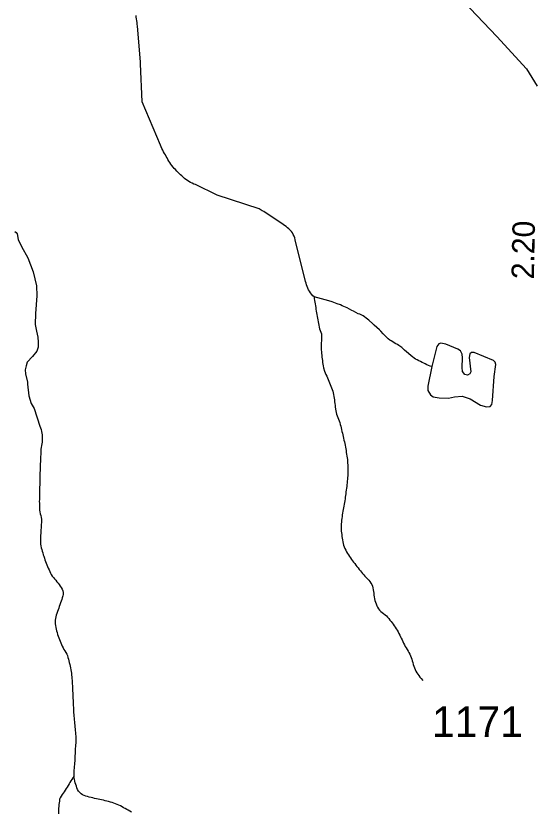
# Model space of a CAD drawing. Extents: x 1950930 to 2061844, y 904556 to 1017002.
# Drawn here: x 1966393 to 1969289, y 930923 to 935352 of the extents above; entities that cross this region are included whole.
import ezdxf

# ---------------------------------------------------------------- set-up
doc = ezdxf.new("R2010")
doc.units = 0
for name, color, linetype in [('Exist Hydrographic Creek Single Shore', 7, 'Continuous'), ('Exist Hydrographic Misc Water Feature', 7, 'Continuous'), ('Exist Road Primary US Structure Standard Bridge CELL', 7, 'Continuous'), ('Exist Road Secondary Type 51 Attributed', 7, 'Continuous'), ('Exist Road Secondary Type 51 Number Label', 7, 'Continuous')]:
    doc.layers.add(name, color=color, linetype=linetype)

msp = doc.modelspace()

# ---------------------------------------------------------------- linework, layer by layer
at = {"layer": 'Exist Hydrographic Creek Single Shore'}
for points in [[(1967068.9, 935305.6), (1967067.1, 935315.4), (1967065.5, 935325.3), (1967064.4, 935335.2), (1967063.2, 935345.1), (1967062.6, 935354.9)], [(1967392.1, 934413.6), (1967382.7, 934417), (1967373.9, 934422.1), (1967364.8, 934426.5), (1967356.2, 934431.6), (1967347.6, 934436.7), (1967339.8, 934442.5), (1967332, 934448.5), (1967324.4, 934455.2), (1967317.1, 934461.9), (1967309.7, 934468.6), (1967302.3, 934476.2), (1967295.1, 934482.8), (1967287.9, 934489.6), (1967281, 934497.1), (1967274.2, 934503.9), (1967267.6, 934511.3), (1967261.3, 934519.6), (1967255.3, 934528), (1967249.8, 934536.4), (1967244.7, 934544.7), (1967239.5, 934553), (1967234.6, 934562.1), (1967229.7, 934570.4), (1967224.8, 934579.5), (1967220.1, 934587.8), (1967214.9, 934596.9), (1967210.4, 934606.1), (1967205.9, 934614.4), (1967201.4, 934623.5), (1967197.1, 934632.5), (1967096.5, 934874.2), (1967086.6, 935086.1), (1967086.6, 935096.9), (1967070.6, 935295.7), (1967068.9, 935305.6)], [(1968052.4, 933789.6), (1968045, 933795.4), (1968039.2, 933803.7), (1968033.3, 933812), (1968028, 933820.4), (1968022.6, 933828.7), (1968018.3, 933837.8), (1968014.4, 933847), (1968011.4, 933856), (1968008.1, 933865.9), (1968005.2, 933875), (1967947.8, 934107.6), (1967944.9, 934117.5), (1967941, 934126.6), (1967936.9, 934135.7), (1967932.4, 934144.8), (1967926.9, 934153.1), (1967920.3, 934160.7), (1967912.7, 934167.4), (1967905.1, 934173.2), (1967897.4, 934180), (1967888.9, 934185.9), (1967880.9, 934191.8), (1967872.5, 934196.9), (1967864.5, 934202.8), (1967856.1, 934208.8), (1967847.9, 934214.7), (1967839.7, 934219.8), (1967831.3, 934225.7), (1967823.3, 934231.5), (1967814.7, 934236.7), (1967806.3, 934242.5), (1967797.9, 934247.6), (1967789.7, 934253.6), (1967781.1, 934258.7), (1967772.9, 934263.8), (1967764.1, 934268.9), (1967746.8, 934279.1), (1967513.1, 934354.5), (1967392.1, 934413.6)], [(1966386.5, 934153.7), (1966393.7, 934147.1), (1966400.1, 934139.6), (1966406.2, 934108.3), (1966424, 934069.3), (1966459, 934007.5), (1966489, 933929.5), (1966506.9, 933851.5), (1966510.1, 933794.7), (1966502, 933696.4), (1966499.6, 933635.5), (1966507.7, 933598), (1966514.2, 933564.7), (1966517.4, 933537.9), (1966516.6, 933510.3), (1966509.3, 933488.3), (1966485.8, 933457.5), (1966455.7, 933425.8), (1966449.2, 933406.3), (1966444.3, 933384.3)], [(1968052.4, 933789.6), (1968054, 933779.7), (1968055.4, 933769.8), (1968057.1, 933759.9), (1968058.7, 933750.1), (1968060.2, 933740.1), (1968061.6, 933730.2), (1968063.2, 933720.3), (1968065.1, 933710.5), (1968066.3, 933700.7), (1968068, 933690.7), (1968069.6, 933680.9), (1968071.2, 933671), (1968073.1, 933661.1), (1968074.7, 933651.2), (1968077, 933641.4), (1968078.8, 933631.5), (1968081.1, 933621.5), (1968083.3, 933611.7), (1968086.8, 933602.5), (1968090.7, 933593.5), (1968094.2, 933583.6), (1968094.8, 933544.2), (1968093, 933534.4), (1968091.5, 933524.5), (1968091.5, 933514.7), (1968092.4, 933504.8), (1968093, 933495), (1968093.8, 933484.3), (1968094.6, 933474.4), (1968095.4, 933464.5), (1968096.7, 933454.7), (1968097.7, 933444.8), (1968098.9, 933434.9), (1968100.4, 933425.1), (1968101.8, 933415.1), (1968103.8, 933405.3), (1968105.7, 933395.4), (1968111, 933376.4), (1968114.7, 933366.5), (1968118.8, 933357.4), (1968123.1, 933348.3), (1968131.3, 933330.1), (1968135, 933321), (1968143.2, 933302.8), (1968146.7, 933293.6), (1968150.6, 933283.7), (1968153.7, 933274.7), (1968156.5, 933264.7), (1968161, 933245.8), (1968162.9, 933235.9), (1968164.3, 933226.1), (1968165.8, 933216.1), (1968166.8, 933206.3), (1968168.2, 933196.4), (1968169.7, 933185.7), (1968170.9, 933175.8), (1968174, 933156.1), (1968176, 933146.2), (1968178.3, 933137.1), (1968184.8, 933118.1), (1968188.7, 933109), (1968192.4, 933099.1), (1968195.7, 933090), (1968198.6, 933080.1), (1968201.2, 933071.1), (1968203.5, 933061.1), (1968205.8, 933051.3), (1968208, 933041.3), (1968210.3, 933031.4), (1968212.7, 933022.4), (1968214.6, 933012.5), (1968216.8, 933002.6), (1968219.1, 932992.7), (1968221.3, 932982.8), (1968223.6, 932972.9), (1968225.8, 932963.8), (1968227.7, 932954), (1968229.3, 932944.1), (1968231, 932934.2), (1968232.2, 932924.3), (1968233.8, 932914.5), (1968235.1, 932903.7), (1968236.7, 932893.9), (1968237.9, 932884), (1968239, 932874.2), (1968239.6, 932864.3), (1968240.2, 932854.4), (1968240.8, 932844.6), (1968241.2, 932834.7), (1968241.2, 932824.9)], [(1966444.3, 933384.3), (1966446.8, 933361.4), (1966457.1, 933315.4), (1966457.3, 933303.7), (1966464.6, 933239.5), (1966478.5, 933195.7), (1966494.7, 933168), (1966526.8, 933070.2), (1966530.3, 933061.2), (1966533.1, 933051.3), (1966535.4, 933041.4), (1966536.8, 933031.5), (1966538.3, 933021.6), (1966539.1, 933011.8), (1966539.5, 933001.9), (1966539.7, 932992.1), (1966539.1, 932981.3), (1966537.7, 932971.6), (1966536.2, 932961.8), (1966534.2, 932951.9), (1966532.5, 932942.2), (1966531.9, 932932.3), (1966531.3, 932922.5), (1966530.9, 932912.6), (1966530.5, 932902), (1966529.7, 932892.1), (1966529.4, 932882.3), (1966529, 932872.5), (1966528.4, 932862.6), (1966528.2, 932852), (1966528, 932842.2), (1966527.4, 932832.3), (1966527.4, 932822.5), (1966526.8, 932812.6), (1966526.8, 932802), (1966526.6, 932792.1), (1966526.2, 932782.3), (1966526.2, 932772.4), (1966526, 932762.7), (1966525.8, 932752.7), (1966525.6, 932742.1), (1966524.9, 932732.2), (1966524.9, 932722.5), (1966524.5, 932712.5), (1966524.5, 932702.8), (1966523.9, 932692.1), (1966523.9, 932682.3), (1966523.7, 932672.4), (1966523.7, 932662.6), (1966523.3, 932651.8), (1966523.7, 932642.1), (1966523.7, 932632.1), (1966523.7, 932622.4), (1966524.3, 932612.5), (1966524.5, 932602.6), (1966526.2, 932592.8), (1966528.4, 932582.8)], [(1968241.2, 932824.9), (1968240.6, 932814.2), (1968240.2, 932804.4), (1968239.8, 932794.5), (1968239, 932784.7), (1968238.4, 932774.9), (1968237.3, 932765), (1968236.3, 932754.5), (1968235.5, 932744.6), (1968234.3, 932734.8), (1968233.2, 932724.9), (1968231.6, 932715.1), (1968230.4, 932705.2), (1968229.1, 932694.7), (1968228.1, 932684.8), (1968226.5, 932675), (1968225.2, 932665.3), (1968223.6, 932655.4), (1968221.9, 932645.6), (1968220.1, 932635.7), (1968218.1, 932626), (1968216.2, 932616.1), (1968214.6, 932606.3), (1968212.7, 932596.6), (1968211.1, 932586.7), (1968209.4, 932576.9), (1968208.2, 932567), (1968206.6, 932556.5), (1968205.5, 932546.6), (1968204.9, 932536.8), (1968204.1, 932526.9), (1968203.5, 932517.1), (1968203.7, 932506.4), (1968203.7, 932496.6), (1968204.3, 932486.8), (1968205.3, 932476.9), (1968206.4, 932467), (1968207.2, 932457.1), (1968208.6, 932447.3), (1968210.5, 932437.4), (1968212.7, 932427.5), (1968215, 932417.7), (1968217.4, 932407.7), (1968220.7, 932398.7), (1968224.8, 932389.6), (1968228.9, 932380.4), (1968233.6, 932371.3), (1968238.4, 932362.2), (1968243.7, 932353.8), (1968249.2, 932345.5), (1968255, 932337.2), (1968260.7, 932328.9), (1968266.9, 932321.4), (1968272.8, 932313.1), (1968278.7, 932305.5), (1968285.3, 932297.2), (1968291.5, 932289.7), (1968297.6, 932282.2), (1968303.8, 932273.8), (1968310.3, 932266.3), (1968316.7, 932258.8), (1968322.8, 932250.4), (1968329, 932242.9), (1968335.5, 932235.5), (1968342.7, 932227.9), (1968349.9, 932220.4), (1968356.7, 932212.9), (1968363.2, 932205.3), (1968369, 932197), (1968373.7, 932188.7), (1968377.4, 932179.6), (1968380, 932170.5), (1968382.1, 932160.6), (1968383.5, 932150.8), (1968384.8, 932140.9), (1968386, 932130.2), (1968387.4, 932120.3), (1968389.3, 932110.5), (1968391.7, 932100.5), (1968394.6, 932090.6), (1968397.7, 932081.6), (1968401.4, 932071.6), (1968405.7, 932062.5), (1968410.8, 932054.2), (1968417, 932046.7), (1968423.9, 932040), (1968431.9, 932033.3), (1968439.9, 932027.3), (1968448.1, 932021.5), (1968455.3, 932014.7), (1968462.1, 932007.2), (1968468.4, 931999.7), (1968475, 931991.3), (1968481.1, 931983.9), (1968487.5, 931975.5), (1968493.4, 931968), (1968499, 931959.7), (1968504.7, 931951.4), (1968510.3, 931943), (1968516, 931934.7)], [(1966528.4, 932582.8), (1966531.7, 932573), (1966534, 932563), (1966535.2, 932553.2), (1966535.2, 932543.3), (1966534.8, 932533.5), (1966534.2, 932523.7), (1966533.6, 932513.8), (1966532.7, 932504), (1966531.9, 932493.3), (1966531.7, 932483.6), (1966531.3, 932473.6), (1966530.7, 932463.9), (1966530.1, 932453.1), (1966529.4, 932443.4), (1966529, 932433.5), (1966529.4, 932422.9), (1966530.1, 932412.9), (1966531.9, 932403.9), (1966534.2, 932394.1), (1966536.8, 932384.1), (1966539.3, 932375), (1966542.2, 932365.2), (1966545, 932355.2), (1966548.3, 932346.2), (1966551.6, 932336.2), (1966554.9, 932327.1), (1966558.4, 932317.3), (1966561.8, 932308.2), (1966565.5, 932299), (1966569.4, 932289.1), (1966573.3, 932280), (1966577.4, 932270.9), (1966581.3, 932261.8), (1966585.8, 932252.7), (1966589.9, 932244.4), (1966595.5, 932236.1), (1966601.4, 932227.8), (1966608.2, 932220.2), (1966615, 932212.7), (1966621.7, 932205.2), (1966628.1, 932197.6), (1966634, 932189.3), (1966639.6, 932181), (1966645.3, 932171.9), (1966650.4, 932162.8), (1966654.5, 932153.6), (1966656.2, 932144.5), (1966656.2, 932134.7), (1966654.3, 932125.8), (1966651, 932115.9), (1966647.8, 932106.2), (1966644.1, 932096.4), (1966640.6, 932086.6), (1966637.7, 932076.9), (1966634.6, 932067), (1966631.2, 932058.1), (1966627.5, 932048.4), (1966624, 932038.5), (1966620.5, 932028.8), (1966617.4, 932019), (1966615, 932009.2), (1966612.9, 932000.3), (1966611.9, 931990.4), (1966611.7, 931980.6), (1966612.3, 931970.7), (1966613.5, 931960.9), (1966615.2, 931951), (1966617.2, 931941.9), (1966619.7, 931932), (1966622.5, 931922.1), (1966625.4, 931912.2), (1966628.7, 931902.3), (1966632, 931893.1), (1966635.5, 931883.3), (1966638.9, 931874.2), (1966642.2, 931864.2), (1966645.9, 931855.2), (1966650.4, 931846.1), (1966655.6, 931837.8), (1966660.7, 931828.6), (1966666, 931820.2), (1966671.1, 931811.1), (1966675.9, 931802.8), (1966679.3, 931793.7), (1966682.2, 931783.8), (1966685.3, 931774.7), (1966688, 931764.9), (1966690.4, 931754.9), (1966693.1, 931745.1), (1966694.9, 931735.1), (1966697, 931725.3), (1966698.8, 931715.5), (1966700.1, 931705.5), (1966701.7, 931695.7), (1966702.7, 931685.8), (1966703.9, 931675.9), (1966705, 931666), (1966705.6, 931656.2), (1966706.4, 931646.3)], [(1968516, 931934.7), (1968520.7, 931926.3), (1968525.4, 931917.2), (1968529.9, 931908.2), (1968534.2, 931899.1), (1968538.1, 931890), (1968542.2, 931880.8), (1968546.3, 931871.8), (1968550.9, 931862.7), (1968555.8, 931854.3), (1968560.7, 931845.1), (1968565.8, 931836.8), (1968570.9, 931827.7), (1968575.9, 931819.4), (1968580.8, 931810.3), (1968585.3, 931802), (1968589.4, 931792.9), (1968592.9, 931783), (1968596.4, 931773.9), (1968599.2, 931764), (1968602.1, 931754.9), (1968605, 931745), (1968608.5, 931735.9), (1968612, 931725.9), (1968615.4, 931716.9), (1968619.5, 931707.8), (1968624.3, 931698.6), (1968629.4, 931690.3), (1968635.3, 931682.8), (1968641.7, 931674.5), (1968648.5, 931667), (1968658.7, 931655.3)], [(1966706.4, 931646.3), (1966706.8, 931636.5), (1966707.4, 931626.6), (1966708, 931616.7), (1966708.5, 931606.1), (1966708.7, 931596.2), (1966709.1, 931586.4), (1966709.7, 931576.5), (1966710.1, 931566.7), (1966710.3, 931555.9), (1966710.9, 931546.2), (1966711.3, 931536.2), (1966711.9, 931526.4), (1966712.6, 931516.6), (1966713, 931505.9), (1966713.6, 931496), (1966713.8, 931486.1), (1966714.2, 931476.4), (1966714.8, 931466.4), (1966715.8, 931456.6), (1966716.5, 931446.7), (1966717.5, 931436.8), (1966718.3, 931426.2), (1966719.3, 931416.4), (1966720.6, 931406.4), (1966721.6, 931396.6), (1966722.8, 931386.8), (1966723.8, 931376.8), (1966724.5, 931367), (1966725.5, 931357.1), (1966726.1, 931346.5), (1966726.7, 931336.6), (1966727.3, 931326.7), (1966726.7, 931316.9), (1966726.1, 931307), (1966725.1, 931297.2), (1966724, 931287.4), (1966723.4, 931276.7), (1966723.2, 931266.9), (1966722.6, 931257.1), (1966722.2, 931247.2), (1966721.6, 931237.4), (1966721.2, 931226.8), (1966721, 931216.9), (1966720.4, 931207.1), (1966719.5, 931197.3), (1966718.7, 931187.3), (1966717.5, 931177.6), (1966716.5, 931166.9), (1966715.2, 931157.1), (1966714.6, 931147.3), (1966714.6, 931137.4), (1966714.8, 931121.8)], [(1966714.8, 931121.8), (1966709.7, 931113.7), (1966704.6, 931104.8), (1966699.4, 931096.8), (1966694.1, 931087.8), (1966688.6, 931079.8), (1966683, 931070.9), (1966678.1, 931062.7), (1966673, 931053.9), (1966667.7, 931045.6), (1966662.3, 931036.7), (1966657, 931028.7), (1966651, 931020.6), (1966644.5, 931012.5), (1966639.4, 931003.6), (1966636.5, 930994.6), (1966634.8, 930984.9), (1966633.2, 930975), (1966632.2, 930965.2), (1966631.4, 930955.4), (1966630.7, 930944.7), (1966630.1, 930934.9), (1966630.1, 930925.1), (1966629.9, 930914.4)], [(1966811.2, 931004.2), (1966801.3, 931006.8), (1966791.9, 931009.6), (1966782.5, 931012.1), (1966773.1, 931014.8), (1966764.2, 931019.1), (1966755.8, 931025), (1966748.2, 931032.5), (1966741.7, 931040.1), (1966736.3, 931048.4), (1966732.9, 931057.5), (1966729.4, 931067.4), (1966726.5, 931077.3), (1966723.6, 931086.4), (1966721.2, 931096.3), (1966718.7, 931106.2), (1966714.8, 931121.8)], [(1967035.9, 930923.2), (1967027.3, 930928.4), (1967018.5, 930933.5), (1967009.9, 930938.5), (1967001.5, 930943.6), (1966992.5, 930947.9), (1966983.6, 930953), (1966974.4, 930957.4), (1966965.6, 930961.7), (1966956.6, 930965.9), (1966947.1, 930969.4), (1966937.7, 930972.9), (1966928.5, 930976.3), (1966918.8, 930979), (1966909.2, 930981.7), (1966899.4, 930984.3), (1966889.9, 930986.9), (1966880.3, 930989.7), (1966870.2, 930991.4), (1966860.4, 930994.2), (1966850.4, 930996), (1966840.7, 930997.9), (1966830.9, 930999.7), (1966821, 931002.3), (1966811.2, 931004.2)]]:
    msp.add_lwpolyline(points, dxfattribs=at)
at = {"layer": 'Exist Hydrographic Misc Water Feature'}
for points in [[(1968707.8, 933401.5), (1968699.7, 933404.5), (1968690.5, 933408), (1968681.1, 933412.3), (1968672, 933416.6), (1968662.8, 933420.9), (1968653.6, 933424.3), (1968644.6, 933429.4), (1968635.7, 933433.8), (1968626.9, 933438.8), (1968618.1, 933443.1), (1968593.9, 933460.9), (1968578.7, 933473.5), (1968556.4, 933493.7), (1968548.8, 933500.3), (1968541.2, 933507.1), (1968524.8, 933518.1), (1968516.2, 933524), (1968507.8, 933529), (1968499.2, 933534.2), (1968490.6, 933539.3), (1968482, 933544.4), (1968473.5, 933549.5), (1968465.3, 933555.4), (1968437, 933583.1), (1968423.7, 933598.1), (1968416.5, 933605.6), (1968402.2, 933619.1), (1968387.4, 933632.5), (1968380, 933639.1), (1968357.9, 933660.2), (1968350.1, 933666), (1968326.5, 933684.6), (1968308.1, 933692.4), (1968298.4, 933695), (1968272, 933709.5), (1968263.2, 933713.8), (1968236.7, 933728.3), (1968227.7, 933732.7), (1968209.4, 933740.3), (1968200.2, 933744.6), (1968181.6, 933751.6), (1968162.5, 933758.6), (1968153.1, 933761.2), (1968134.2, 933767.3), (1968114.9, 933772.6), (1968052.4, 933789.6)], [(1968707.8, 933401.5), (1968685.4, 933292.3), (1968685.4, 933267.9), (1968700.8, 933244.3), (1968715.4, 933233.8), (1968749.5, 933227.3), (1968800.7, 933226.5), (1968834, 933233.8), (1968877, 933236.2), (1968920.9, 933222.4), (1968979.4, 933186.7), (1969012.6, 933177.7), (1969032.1, 933180.2), (1969041.9, 933189.9), (1969046.8, 933212.7), (1969055.7, 933345.9), (1969063.8, 933412.5), (1969061.4, 933425.5), (1969051.6, 933435.3), (1968944.4, 933480.8), (1968928.2, 933480), (1968919.3, 933472.7), (1968915.2, 933452.4), (1968924.9, 933371.9), (1968920.1, 933362.2), (1968907.1, 933354.8), (1968891.6, 933358.1), (1968879.5, 933373.5), (1968877, 933397.1), (1968879.5, 933449.9), (1968877.8, 933471), (1968867.3, 933489.7), (1968852.7, 933497.9), (1968786.9, 933525.5), (1968758.5, 933531.2), (1968747.1, 933527.9), (1968736.5, 933513.3), (1968707.8, 933401.5)]]:
    msp.add_lwpolyline(points, dxfattribs=at)
at = {"layer": 'Exist Road Secondary Type 51 Attributed'}
msp.add_lwpolyline([(1968772.5, 935551), (1969069.1, 935237.4), (1969235.4, 935057.8), (1969294.1, 934961.4)], dxfattribs=at)

# ---------------------------------------------------------------- texts
at = {"layer": 'Exist Road Primary US Structure Standard Bridge CELL'}
msp.add_text('2.20', height=125, rotation=88.9037, dxfattribs=at).set_placement((1969276.4, 933886.5))
at = {"layer": 'Exist Road Secondary Type 51 Number Label'}
msp.add_text('1171', height=170, dxfattribs=at).set_placement((1968709.4, 931341.3))

doc.saveas('drawing.dxf')
